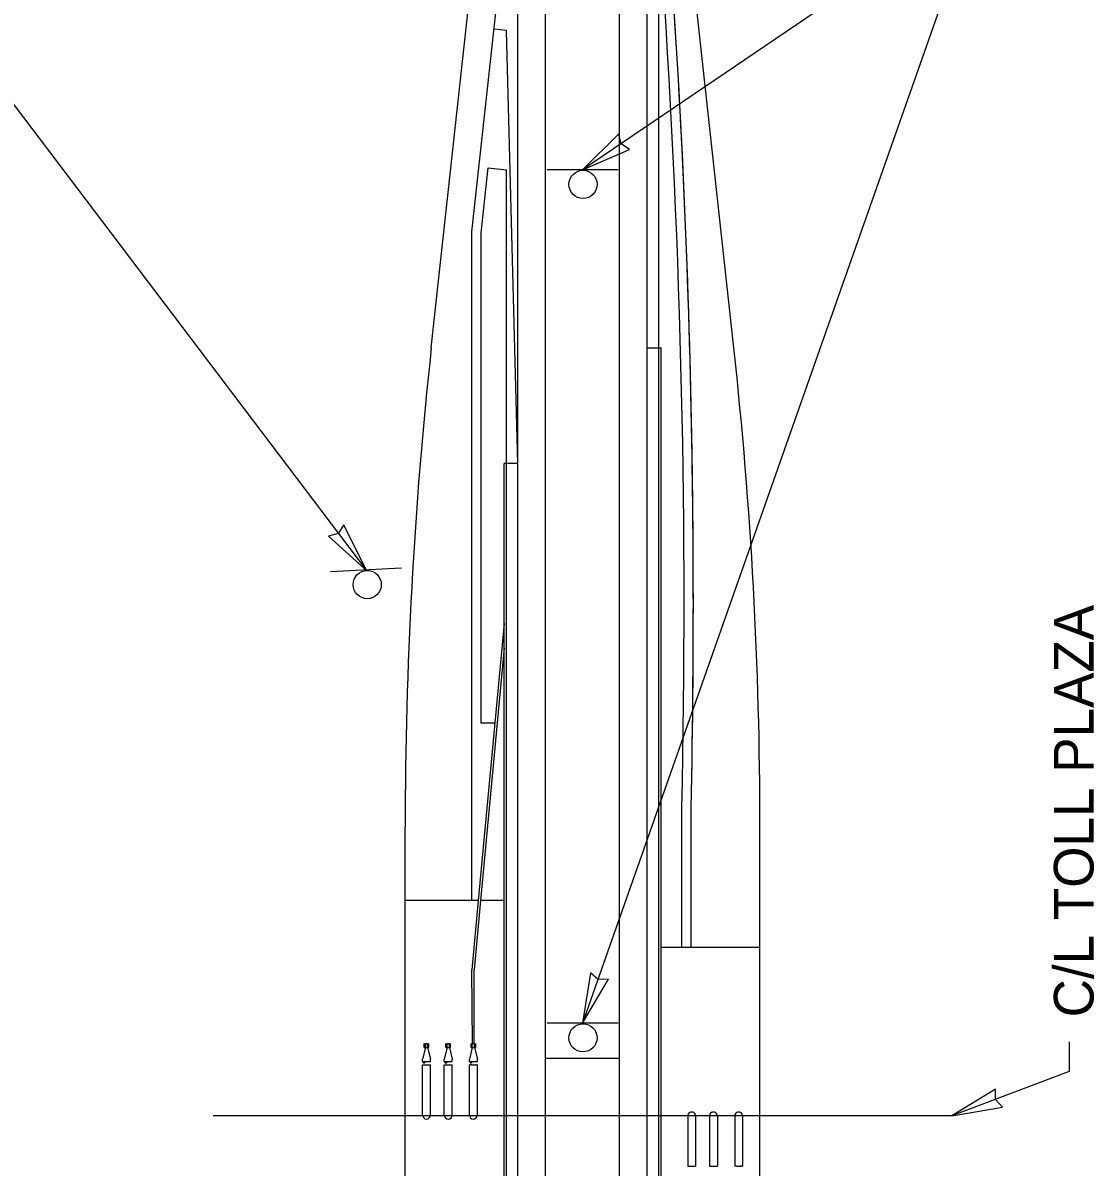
# Model space of a CAD drawing. Extents: x -102308 to -98250, y 54554 to 62383.
# Drawn here: x -101036 to -100108, y 56510 to 57501 of the extents above; entities that cross this region are included whole.
import ezdxf

# ---------------------------------------------------------------- set-up
doc = ezdxf.new("R2010")
doc.units = 0
for name, color, linetype in [('Default', 7, 'Continuous'), ('LeaderLine_dp', 7, 'Continuous'), ('RoadwayMisc', 7, 'Continuous'), ('SignSupport', 7, 'Continuous'), ('TextLabel', 7, 'Continuous')]:
    doc.layers.add(name, color=color, linetype=linetype)

msp = doc.modelspace()

# ---------------------------------------------------------------- linework, layer by layer
at = {"layer": 'Default'}
msp.add_line((-100230.78, 56554.62), (-100870.78, 56554.62), dxfattribs=at)
at = {"layer": 'LeaderLine_dp'}
for p, q in [((-100209.35, 57605.31), (-100550.73, 56634.83)), ((-100209.35, 57605.31), (-100550.73, 57373.9)), ((-101108.2, 57515.43), (-100737.95, 57026.88)), ((-100519.27, 57405.02), (-100550.73, 57373.9)), ((-100517.45, 57396.46), (-100519.27, 57405.02)), ((-100550.73, 57373.9), (-100510.01, 57391.36)), ((-100510.01, 57391.36), (-100517.45, 57396.46)), ((-100757.67, 57066.55), (-100762.35, 57058.83)), ((-100737.95, 57026.88), (-100757.67, 57066.55)), ((-100762.35, 57058.83), (-100770.79, 57056.54)), ((-100770.79, 57056.54), (-100737.95, 57026.88)), ((-100543.94, 56678.55), (-100550.73, 56634.83)), ((-100537.39, 56672.75), (-100543.94, 56678.55)), ((-100550.73, 56634.83), (-100528.37, 56673.08)), ((-100528.37, 56673.08), (-100537.39, 56672.75)), ((-100129.18, 56618.87), (-100129.18, 56593.2)), ((-100129.18, 56593.2), (-100230.78, 56554.62)), ((-100192.99, 56577.64), (-100230.78, 56554.62)), ((-100193.2, 56568.89), (-100192.99, 56577.64)), ((-100187.13, 56562.21), (-100193.2, 56568.89)), ((-100230.78, 56554.62), (-100187.13, 56562.21))]:
    msp.add_line(p, q, dxfattribs=at)
at = {"layer": 'RoadwayMisc'}
for p, q in [((-100582.78, 55117.42), (-100582.78, 62374.01)), ((-100518.78, 55119.1), (-100518.78, 62374.01)), ((-100494.78, 55409.74), (-100494.78, 57849.73)), ((-100646.71, 57320.05), (-100606.78, 57685.42)), ((-100606.78, 57119.62), (-100606.78, 57685.42)), ((-100681.83, 57219.61), (-100641.39, 57589.63)), ((-100419.73, 57219.61), (-100460.17, 57589.63)), ((-100484.78, 57219.62), (-100484.78, 57542.62)), ((-100616.78, 57494.59), (-100627.51, 57495.74)), ((-100606.78, 57119.62), (-100616.78, 57494.59)), ((-100638.76, 57319.18), (-100632.59, 57375.6)), ((-100632.59, 57375.6), (-100616.78, 57373.9)), ((-100616.78, 57119.62), (-100616.78, 57373.9)), ((-100646.71, 56741.25), (-100646.71, 57320.05)), ((-100638.71, 56894.62), (-100638.71, 57320.05)), ((-100494.78, 57219.63), (-100484.78, 57219.62)), ((-100484.78, 57219.63), (-100482.78, 57219.63)), ((-100484.78, 55939.63), (-100484.78, 57219.63)), ((-100482.78, 55689.04), (-100482.78, 57219.63)), ((-100618.79, 56019.62), (-100618.79, 57119.63)), ((-100616.69, 57119.63), (-100618.69, 57119.63)), ((-100616.78, 56019.62), (-100616.79, 57119.62)), ((-100606.78, 57119.63), (-100615.69, 57119.63)), ((-100606.78, 56019.62), (-100606.78, 57119.63)), ((-100618.79, 56981.12), (-100641.14, 56741.01)), ((-100618.79, 56959.55), (-100639.13, 56741.01)), ((-100626.84, 56894.62), (-100638.71, 56894.62)), ((-100464.78, 56700.68), (-100464.77, 56821.18)), ((-100456.78, 56700.68), (-100456.77, 56821.18)), ((-100704.44, 56486.13), (-100704.44, 56804.62)), ((-100397.12, 56304.62), (-100397.12, 56804.62)), ((-100641.14, 56741.01), (-100704.44, 56741.01)), ((-100641.14, 56741.01), (-100646.71, 56681.13)), ((-100639.13, 56741.01), (-100644.71, 56681.03)), ((-100618.79, 56741.01), (-100639.13, 56741.01)), ((-100482.78, 56700.59), (-100397.12, 56700.59)), ((-100646.19, 56617.23), (-100646.71, 56681.13)), ((-100644.69, 56617.56), (-100644.71, 56681.03)), ((-100686.97, 56613.77), (-100689.38, 56603.77)), ((-100687.97, 56613.77), (-100687.97, 56617.26)), ((-100687.97, 56613.77), (-100686.97, 56613.77)), ((-100686.97, 56613.77), (-100686.97, 56617.26)), ((-100686.97, 56617.26), (-100684.97, 56617.26)), ((-100686.97, 56613.77), (-100684.97, 56613.77)), ((-100684.97, 56613.77), (-100684.97, 56617.26)), ((-100684.97, 56613.77), (-100682.55, 56603.77)), ((-100683.97, 56613.77), (-100684.97, 56613.77)), ((-100683.97, 56613.77), (-100683.97, 56617.26)), ((-100668.14, 56613.77), (-100670.56, 56603.77)), ((-100669.14, 56613.77), (-100669.14, 56617.26)), ((-100669.14, 56613.77), (-100668.14, 56613.77)), ((-100668.14, 56613.77), (-100668.14, 56617.26)), ((-100668.14, 56617.26), (-100666.14, 56617.26)), ((-100668.14, 56613.77), (-100666.14, 56613.77)), ((-100666.14, 56613.77), (-100666.14, 56617.26)), ((-100666.14, 56613.77), (-100663.73, 56603.77)), ((-100665.14, 56613.77), (-100666.14, 56613.77)), ((-100665.14, 56613.77), (-100665.14, 56617.26)), ((-100646.32, 56613.77), (-100648.73, 56603.77)), ((-100647.32, 56613.77), (-100647.32, 56617.26)), ((-100647.32, 56613.77), (-100646.32, 56613.77)), ((-100646.32, 56613.77), (-100646.32, 56617.26)), ((-100646.32, 56617.26), (-100644.32, 56617.26)), ((-100646.32, 56613.77), (-100644.32, 56613.77)), ((-100644.32, 56613.77), (-100644.32, 56617.26)), ((-100643.32, 56613.77), (-100644.32, 56613.77)), ((-100644.32, 56613.77), (-100641.9, 56603.77)), ((-100643.32, 56613.77), (-100643.32, 56617.26)), ((-100689.39, 56598.77), (-100682.56, 56598.77)), ((-100689.39, 56555.12), (-100689.39, 56598.77)), ((-100689.38, 56601.77), (-100689.38, 56603.77)), ((-100689.38, 56601.77), (-100682.55, 56601.77)), ((-100688.58, 56601.19), (-100687.58, 56601.19)), ((-100688.58, 56600.19), (-100688.58, 56601.19)), ((-100687.58, 56600.19), (-100688.58, 56600.19)), ((-100687.58, 56601.19), (-100687.58, 56600.19)), ((-100682.56, 56555.12), (-100682.56, 56598.77)), ((-100682.55, 56601.77), (-100682.55, 56603.77)), ((-100670.56, 56601.77), (-100670.56, 56603.77)), ((-100670.56, 56601.77), (-100663.73, 56601.77)), ((-100670.56, 56555.12), (-100670.56, 56598.77)), ((-100670.56, 56598.77), (-100663.73, 56598.77)), ((-100669.76, 56601.19), (-100668.76, 56601.19)), ((-100669.76, 56600.19), (-100669.76, 56601.19)), ((-100668.76, 56600.19), (-100669.76, 56600.19)), ((-100668.76, 56601.19), (-100668.76, 56600.19)), ((-100663.73, 56601.77), (-100663.73, 56603.77)), ((-100663.73, 56555.12), (-100663.73, 56598.77)), ((-100648.74, 56555.12), (-100648.74, 56598.77)), ((-100647.98, 56598.77), (-100648.74, 56598.77)), ((-100648.73, 56601.77), (-100648.73, 56603.77)), ((-100648.73, 56601.77), (-100641.9, 56601.77)), ((-100646.98, 56598.77), (-100647.98, 56598.77)), ((-100647.93, 56601.19), (-100646.93, 56601.19)), ((-100647.93, 56600.19), (-100647.93, 56601.19)), ((-100646.93, 56600.19), (-100647.93, 56600.19)), ((-100646.98, 56598.77), (-100643.65, 56598.77)), ((-100646.93, 56601.19), (-100646.93, 56600.19)), ((-100643.65, 56598.69), (-100643.82, 56598.69)), ((-100642.65, 56598.77), (-100643.65, 56598.77)), ((-100642.65, 56598.77), (-100641.91, 56598.77)), ((-100641.91, 56555.12), (-100641.91, 56598.77)), ((-100641.9, 56601.77), (-100641.9, 56603.77)), ((-100582.78, 56604.62), (-100518.78, 56604.62)), ((-100459.65, 56554.62), (-100459.65, 56510.97)), ((-100452.82, 56554.62), (-100452.82, 56510.98)), ((-100440.82, 56554.62), (-100440.82, 56510.98)), ((-100433.99, 56554.62), (-100433.99, 56510.98)), ((-100419, 56554.62), (-100419, 56510.98)), ((-100412.17, 56554.62), (-100412.17, 56510.98)), ((-100459.65, 56510.97), (-100452.82, 56510.98)), ((-100440.82, 56510.98), (-100433.99, 56510.98)), ((-100418.24, 56510.98), (-100419, 56510.98)), ((-100417.24, 56510.98), (-100418.24, 56510.98)), ((-100417.24, 56510.98), (-100413.91, 56510.98)), ((-100413.91, 56511.06), (-100414.08, 56511.06)), ((-100412.91, 56510.98), (-100413.91, 56510.98)), ((-100412.91, 56510.98), (-100412.17, 56510.98))]:
    msp.add_line(p, q, dxfattribs=at)
for centre, radius, start, end in [((-108454.83, 56997.32), 8000, 358.738391, 5.072322), ((-108454.83, 56997.32), 8000, 358.738391, 4.896535), ((-108454.83, 56997.32), 7992, 358.738391, 3.912422), ((-96884.72, 56804.62), 3819.72, 173.76281, 179.99998), ((-104216.84, 56804.63), 3819.72, 359.99998, 6.23715), ((-100685.97, 56555.29), 3.42, 180.00001, 0.00001), ((-100667.15, 56555.29), 3.42, 180.00001, 0.00001), ((-100645.32, 56555.29), 3.42, 180.00001, 0.00001), ((-100456.23, 56554.46), 3.42, 0.00001, 180.00001), ((-100437.41, 56554.46), 3.42, 0.00001, 180.00001), ((-100415.58, 56554.46), 3.42, 0.00001, 180.00001)]:
    msp.add_arc(centre, radius, start, end, dxfattribs=at)
at = {"layer": 'SignSupport'}
for p, q in [((-100519.87, 57373.9), (-100581.59, 57373.9)), ((-100707.48, 57028.89), (-100769.11, 57025.66)), ((-100519.87, 56634.83), (-100581.59, 56634.83))]:
    msp.add_line(p, q, dxfattribs=at)
for centre in [(-100550.41, 57361.28), (-100737.31, 57014.69), (-100550.41, 56622.21)]:
    msp.add_circle(centre, 12.21, dxfattribs=at)

# ---------------------------------------------------------------- texts
at = {"layer": 'TextLabel'}
msp.add_text('C/L TOLL PLAZA', height=34.335, rotation=90, dxfattribs=at).set_placement((-100108.16, 56639.92))

doc.saveas('drawing.dxf')
